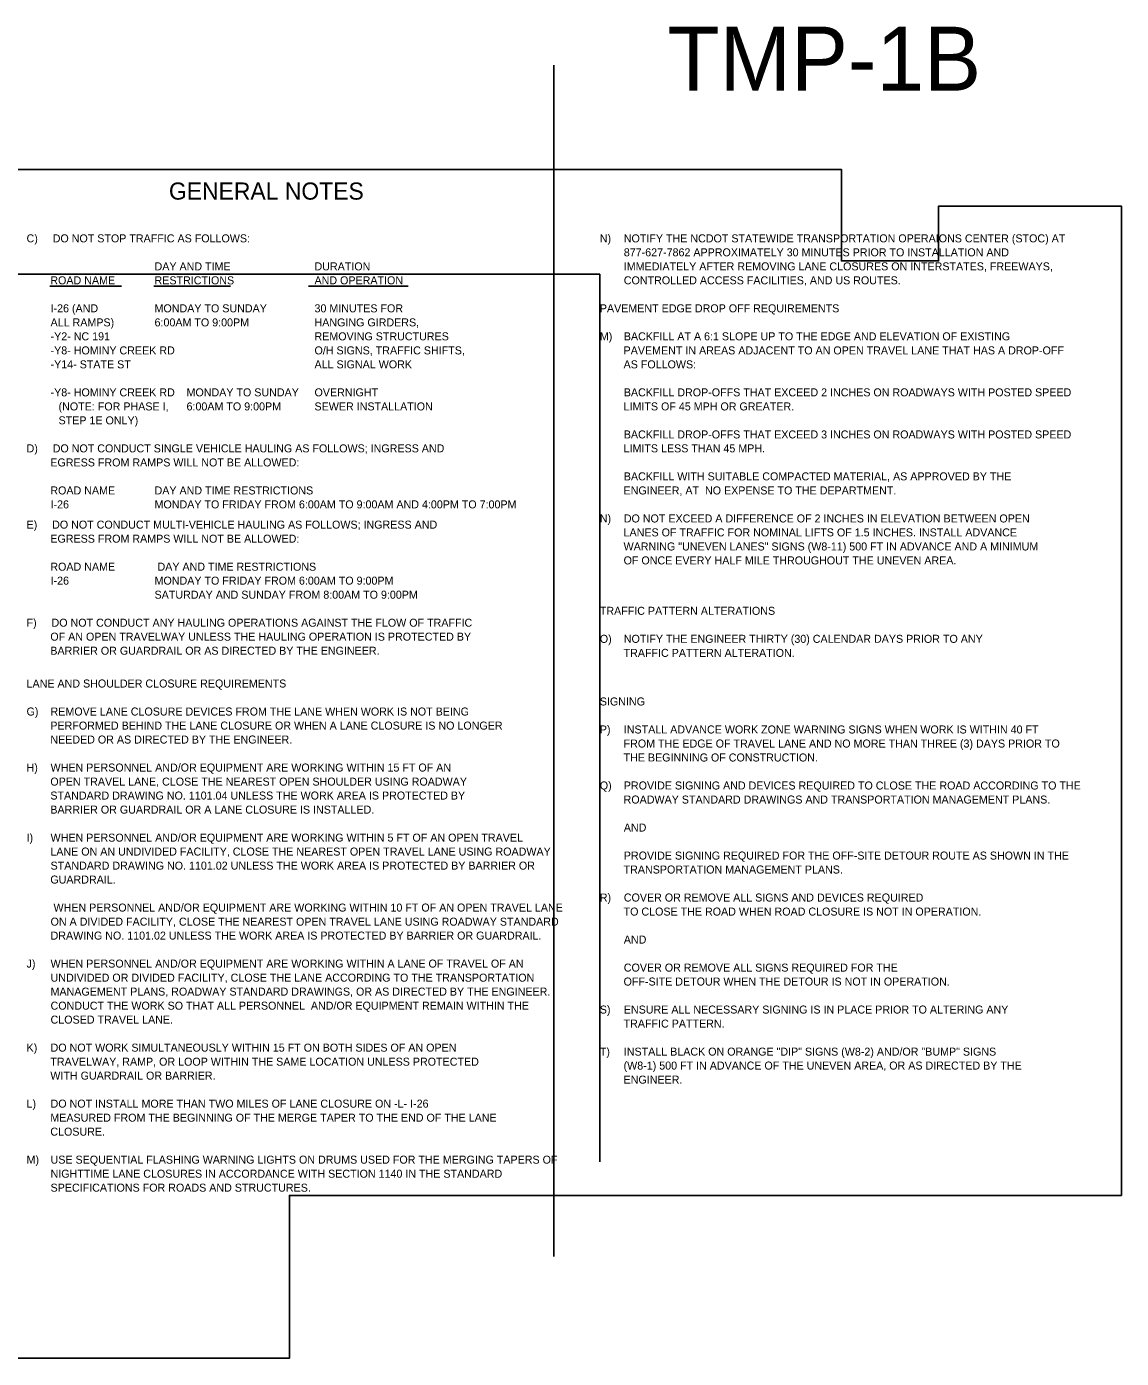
# Model space of a CAD drawing. Extents: x 2485109 to 2490507, y 368607 to 371384.
# Drawn here: x 2487548 to 2488507, y 370218 to 371383 of the extents above; entities that cross this region are included whole.
import ezdxf

# ---------------------------------------------------------------- set-up
doc = ezdxf.new("R2010")
doc.units = 0
for name, color, linetype in [('Scratch_Level_2', 7, 'Continuous'), ('Scratch_Level_4', 7, 'Continuous'), ('TC SHEET LAYOUT SHAPE', 7, 'Continuous'), ('TC SHEET TEXT', 7, 'Continuous'), ('TCP Linework', 7, 'Continuous')]:
    doc.layers.add(name, color=color, linetype=linetype)

msp = doc.modelspace()

# ---------------------------------------------------------------- linework, layer by layer
at = {"layer": 'Scratch_Level_2'}
msp.add_line((2488009.9, 370307.3), (2488009.9, 371349.4), dxfattribs=at)
at = {"layer": 'Scratch_Level_4'}
for p, q in [((2487040.7, 371166.6), (2488050.1, 371166.6)), ((2488050.1, 371166.6), (2488050.1, 370390.1))]:
    msp.add_line(p, q, dxfattribs=at)
at = {"layer": 'TC SHEET LAYOUT SHAPE'}
msp.add_lwpolyline([(2487016.6, 370666.8), (2487016.6, 370976.2), (2487016.6, 371248.3), (2487026.6, 371258.3), (2487469.6, 371258.3), (2487940.6, 371258.3), (2488261.6, 371258.3), (2488261.6, 371178.3), (2488346.6, 371178.3), (2488346.6, 371226.3), (2488506.6, 371226.3), (2488506.6, 370891.3), (2488506.6, 370612.1), (2488506.6, 370360.8), (2487778.4, 370360.8), (2487778.4, 370218.3), (2487608.9, 370218.3), (2487256.1, 370218.3), (2487016.6, 370218.3)], close=True, dxfattribs=at)
at = {"layer": 'TCP Linework'}
for p, q in [((2487568.7, 371156.1), (2487570.7, 371156.1)), ((2487568.7, 371156.1), (2487570.7, 371156.1)), ((2487570.7, 371156.1), (2487631.6, 371156.1)), ((2487659.8, 371156.1), (2487727, 371156.1)), ((2487795.2, 371156.1), (2487882.3, 371156.1))]:
    msp.add_line(p, q, dxfattribs=at)

# ---------------------------------------------------------------- texts
at = {"layer": 'TC SHEET LAYOUT SHAPE'}
msp.add_text('TMP-1B', height=56, rotation=0.0001, dxfattribs=at).set_placement((2488109.2, 371327.2))
at = {"layer": 'TC SHEET TEXT'}
msp.add_text('GENERAL NOTES', height=15, rotation=359.994, dxfattribs=at).set_placement((2487673, 371231.9))
for s, p in [('C)     DO NOT STOP TRAFFIC AS FOLLOWS:', (2487548.4, 371194.5)), ('N)', (2488050.1, 371194.5)), ('NOTIFY THE NCDOT STATEWIDE TRANSPORTATION OPERAIONS CENTER (STOC) AT', (2488071.1, 371194.5)), ('877-627-7862 APPROXIMATELY 30 MINUTES PRIOR TO INSTALLATION AND', (2488071.1, 371182.3)), ('DAY AND TIME', (2487660.4, 371170)), ('DURATION', (2487800.4, 371170)), ('IMMEDIATELY AFTER REMOVING LANE CLOSURES ON INTERSTATES, FREEWAYS,', (2488071.1, 371170)), ('        ROAD NAME ', (2487548.4, 371157.8)), ('RESTRICTIONS ', (2487660.4, 371157.8)), ('AND OPERATION', (2487800.4, 371157.8)), ('CONTROLLED ACCESS FACILITIES, AND US ROUTES.', (2488071.1, 371157.8)), ('I-26 (AND', (2487569.4, 371133.3)), ('MONDAY TO SUNDAY', (2487660.4, 371133.3)), ('30 MINUTES FOR', (2487800.4, 371133.3)), ('PAVEMENT EDGE DROP OFF REQUIREMENTS', (2488050.1, 371133.3)), ('ALL RAMPS)', (2487569.4, 371121)), ('6:00AM TO 9:00PM', (2487660.4, 371121)), ('HANGING GIRDERS,', (2487800.4, 371121)), ('-Y2- NC 191        ', (2487569.4, 371108.8)), ('REMOVING STRUCTURES', (2487800.4, 371108.8)), ('M)', (2488050.1, 371108.8)), ('BACKFILL AT A 6:1 SLOPE UP TO THE EDGE AND ELEVATION OF EXISTING', (2488071.1, 371108.8)), ('-Y8- HOMINY CREEK RD', (2487569.4, 371096.5)), ('O/H SIGNS, TRAFFIC SHIFTS,', (2487800.4, 371096.5)), ('        PAVEMENT IN AREAS ADJACENT TO AN OPEN TRAVEL LANE THAT HAS A DROP-OFF', (2488050.1, 371096.5)), ('-Y14- STATE ST', (2487569.4, 371084.3)), ('ALL SIGNAL WORK', (2487800.4, 371084.3)), ('        AS FOLLOWS: ', (2488050.1, 371084.3)), ('-Y8- HOMINY CREEK RD', (2487569.4, 371059.8)), ('MONDAY TO SUNDAY', (2487688.4, 371059.8)), ('OVERNIGHT', (2487800.4, 371059.8)), ('BACKFILL DROP-OFFS THAT EXCEED 2 INCHES ON ROADWAYS WITH POSTED SPEED', (2488071.1, 371059.8)), ('(NOTE: FOR PHASE I, ', (2487576.4, 371047.5)), ('6:00AM TO 9:00PM', (2487688.4, 371047.5)), ('SEWER INSTALLATION', (2487800.4, 371047.5)), ('        LIMITS OF 45 MPH OR GREATER.', (2488050.1, 371047.5)), ('STEP 1E ONLY)', (2487576.4, 371035.3)), ('BACKFILL DROP-OFFS THAT EXCEED 3 INCHES ON ROADWAYS WITH POSTED SPEED', (2488071.1, 371023)), ('D)     DO NOT CONDUCT SINGLE VEHICLE HAULING AS FOLLOWS; INGRESS AND', (2487548.4, 371010.8)), ('        LIMITS LESS THAN 45 MPH.', (2488050.1, 371010.8)), ('        EGRESS FROM RAMPS WILL NOT BE ALLOWED:', (2487548.4, 370998.5)), ('BACKFILL WITH SUITABLE COMPACTED MATERIAL, AS APPROVED BY THE', (2488071.1, 370986.3)), ('        ROAD NAME ', (2487548.4, 370974)), ('DAY AND TIME RESTRICTIONS', (2487660.4, 370974)), ('        ENGINEER, AT  NO EXPENSE TO THE DEPARTMENT.', (2488050.1, 370974)), ('I-26', (2487569.4, 370961.8)), ('MONDAY TO FRIDAY FROM 6:00AM TO 9:00AM AND 4:00PM TO 7:00PM', (2487660.4, 370961.8)), ('N)', (2488050.1, 370949.5)), ('DO NOT EXCEED A DIFFERENCE OF 2 INCHES IN ELEVATION BETWEEN OPEN', (2488071.1, 370949.5)), ('E)     DO NOT CONDUCT MULTI-VEHICLE HAULING AS FOLLOWS; INGRESS AND', (2487548.4, 370944.1)), ('        LANES OF TRAFFIC FOR NOMINAL LIFTS OF 1.5 INCHES. INSTALL ADVANCE', (2488050.1, 370937.3)), ('        EGRESS FROM RAMPS WILL NOT BE ALLOWED:', (2487548.4, 370931.8)), ('        WARNING "UNEVEN LANES" SIGNS (W8-11) 500 FT IN ADVANCE AND A MINIMUM', (2488050.1, 370925)), ('        ROAD NAME', (2487548.4, 370907.3)), (' DAY AND TIME RESTRICTIONS', (2487660.4, 370907.3)), ('        OF ONCE EVERY HALF MILE THROUGHOUT THE UNEVEN AREA.', (2488050.1, 370912.8)), ('I-26', (2487569.4, 370895.1)), ('MONDAY TO FRIDAY FROM 6:00AM TO 9:00PM', (2487660.4, 370895.1)), ('SATURDAY AND SUNDAY FROM 8:00AM TO 9:00PM', (2487660.4, 370882.8)), ('TRAFFIC PATTERN ALTERATIONS', (2488050.1, 370868.7)), ('F)     DO NOT CONDUCT ANY HAULING OPERATIONS AGAINST THE FLOW OF TRAFFIC', (2487548.4, 370858.3)), ('        OF AN OPEN TRAVELWAY UNLESS THE HAULING OPERATION IS PROTECTED BY', (2487548.4, 370846.1)), ('O)', (2488050.1, 370844.2)), ('NOTIFY THE ENGINEER THIRTY (30) CALENDAR DAYS PRIOR TO ANY', (2488071.1, 370844.2)), ('        BARRIER OR GUARDRAIL OR AS DIRECTED BY THE ENGINEER.', (2487548.4, 370833.8)), ('        TRAFFIC PATTERN ALTERATION.', (2488050.1, 370831.9)), ('LANE AND SHOULDER CLOSURE REQUIREMENTS', (2487548.4, 370805.1)), ('SIGNING', (2488050.1, 370789.4)), ('G)', (2487548.4, 370780.6)), ('REMOVE LANE CLOSURE DEVICES FROM THE LANE WHEN WORK IS NOT BEING', (2487569.4, 370780.6)), ('        PERFORMED BEHIND THE LANE CLOSURE OR WHEN A LANE CLOSURE IS NO LONGER', (2487548.4, 370768.3)), ('P)', (2488050.1, 370764.9)), ('INSTALL ADVANCE WORK ZONE WARNING SIGNS WHEN WORK IS WITHIN 40 FT', (2488071.1, 370764.9)), ('        NEEDED OR AS DIRECTED BY THE ENGINEER.', (2487548.4, 370756.1)), ('        FROM THE EDGE OF TRAVEL LANE AND NO MORE THAN THREE (3) DAYS PRIOR TO', (2488050.1, 370752.6)), ('        THE BEGINNING OF CONSTRUCTION.', (2488050.1, 370740.4)), ('H)', (2487548.4, 370731.6)), ('WHEN PERSONNEL AND/OR EQUIPMENT ARE WORKING WITHIN 15 FT OF AN', (2487569.4, 370731.6)), ('        OPEN TRAVEL LANE, CLOSE THE NEAREST OPEN SHOULDER USING ROADWAY', (2487548.4, 370719.3)), ('Q)', (2488050.1, 370715.9)), ('PROVIDE SIGNING AND DEVICES REQUIRED TO CLOSE THE ROAD ACCORDING TO THE', (2488071.1, 370715.9)), ('        STANDARD DRAWING NO. 1101.04 UNLESS THE WORK AREA IS PROTECTED BY', (2487548.4, 370707.1)), ('        BARRIER OR GUARDRAIL OR A LANE CLOSURE IS INSTALLED.', (2487548.4, 370694.8)), ('        ROADWAY STANDARD DRAWINGS AND TRANSPORTATION MANAGEMENT PLANS.', (2488050.1, 370703.6)), ('I)', (2487548.4, 370670.3)), ('WHEN PERSONNEL AND/OR EQUIPMENT ARE WORKING WITHIN 5 FT OF AN OPEN TRAVEL', (2487569.4, 370670.3)), ('AND', (2488071.1, 370679.1)), ('        LANE ON AN UNDIVIDED FACILITY, CLOSE THE NEAREST OPEN TRAVEL LANE USING ROADWAY', (2487548.4, 370658.1)), ('STANDARD DRAWING NO. 1101.02 UNLESS THE WORK AREA IS PROTECTED BY BARRIER OR', (2487569.4, 370645.8)), ('PROVIDE SIGNING REQUIRED FOR THE OFF-SITE DETOUR ROUTE AS SHOWN IN THE', (2488071.1, 370654.6)), ('        TRANSPORTATION MANAGEMENT PLANS.', (2488050.1, 370642.4)), ('        GUARDRAIL.', (2487548.4, 370633.6)), ('R)', (2488050.1, 370617.9)), ('COVER OR REMOVE ALL SIGNS AND DEVICES REQUIRED', (2488071.1, 370617.9)), (' WHEN PERSONNEL AND/OR EQUIPMENT ARE WORKING WITHIN 10 FT OF AN OPEN TRAVEL LANE', (2487569.4, 370609.1)), ('        TO CLOSE THE ROAD WHEN ROAD CLOSURE IS NOT IN OPERATION.', (2488050.1, 370605.6)), ('ON A DIVIDED FACILITY, CLOSE THE NEAREST OPEN TRAVEL LANE USING ROADWAY STANDARD', (2487569.4, 370596.8)), ('DRAWING NO. 1101.02 UNLESS THE WORK AREA IS PROTECTED BY BARRIER OR GUARDRAIL.', (2487569.4, 370584.6)), ('AND', (2488071.1, 370581.1)), ('J)', (2487548.4, 370560.1)), ('WHEN PERSONNEL AND/OR EQUIPMENT ARE WORKING WITHIN A LANE OF TRAVEL OF AN', (2487569.4, 370560.1)), ('COVER OR REMOVE ALL SIGNS REQUIRED FOR THE', (2488071.1, 370556.6)), ('UNDIVIDED OR DIVIDED FACILITY, CLOSE THE LANE ACCORDING TO THE TRANSPORTATION', (2487569.4, 370547.8)), ('        OFF-SITE DETOUR WHEN THE DETOUR IS NOT IN OPERATION.', (2488050.1, 370544.4)), ('MANAGEMENT PLANS, ROADWAY STANDARD DRAWINGS, OR AS DIRECTED BY THE ENGINEER.', (2487569.4, 370535.6)), ('CONDUCT THE WORK SO THAT ALL PERSONNEL  AND/OR EQUIPMENT REMAIN WITHIN THE', (2487569.4, 370523.3)), ('S)', (2488050.1, 370519.9)), ('ENSURE ALL NECESSARY SIGNING IS IN PLACE PRIOR TO ALTERING ANY', (2488071.1, 370519.9)), ('CLOSED TRAVEL LANE.', (2487569.4, 370511.1)), ('        TRAFFIC PATTERN.', (2488050.1, 370507.6)), ('K)', (2487548.4, 370486.6)), ('DO NOT WORK SIMULTANEOUSLY WITHIN 15 FT ON BOTH SIDES OF AN OPEN', (2487569.4, 370486.6)), ('T)', (2488050.1, 370483.1)), ('INSTALL BLACK ON ORANGE "DIP" SIGNS (W8-2) AND/OR "BUMP" SIGNS', (2488071.1, 370483.1)), ('        TRAVELWAY, RAMP, OR LOOP WITHIN THE SAME LOCATION UNLESS PROTECTED', (2487548.4, 370474.3)), ('        (W8-1) 500 FT IN ADVANCE OF THE UNEVEN AREA, OR AS DIRECTED BY THE', (2488050.1, 370470.9)), ('        WITH GUARDRAIL OR BARRIER.', (2487548.4, 370462.1)), ('        ENGINEER.', (2488050.1, 370458.6)), ('L)', (2487548.4, 370437.6)), ('DO NOT INSTALL MORE THAN TWO MILES OF LANE CLOSURE ON -L- I-26', (2487569.4, 370437.6)), ('        MEASURED FROM THE BEGINNING OF THE MERGE TAPER TO THE END OF THE LANE', (2487548.4, 370425.3)), ('        CLOSURE.', (2487548.4, 370413.1)), ('M)', (2487548.4, 370388.6)), ('USE SEQUENTIAL FLASHING WARNING LIGHTS ON DRUMS USED FOR THE MERGING TAPERS OF', (2487569.4, 370388.6)), ('NIGHTTIME LANE CLOSURES IN ACCORDANCE WITH SECTION 1140 IN THE STANDARD', (2487569.4, 370376.3)), ('SPECIFICATIONS FOR ROADS AND STRUCTURES.', (2487569.4, 370364.1))]:
    msp.add_text(s, height=7, dxfattribs=at).set_placement(p)

doc.saveas('drawing.dxf')
